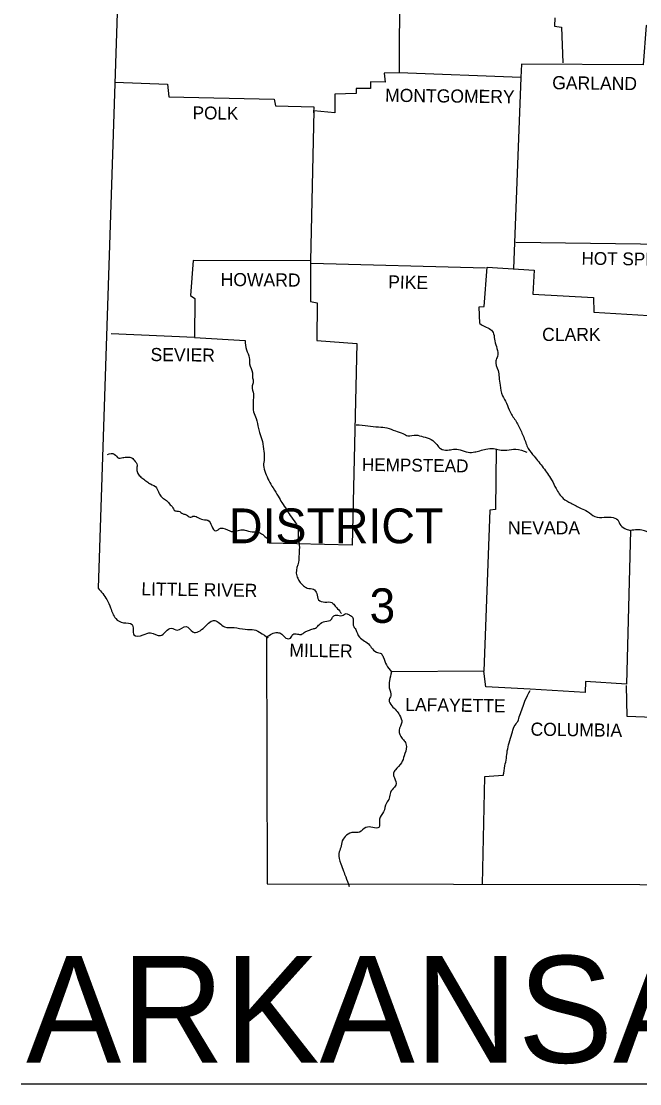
# Model space of a CAD drawing. Extents: x -42408 to 34530, y -43140 to 20491.
# Drawn here: x -17742 to -16626, y 2539 to 4456 of the extents above; entities that cross this region are included whole.
import ezdxf

# ---------------------------------------------------------------- set-up
doc = ezdxf.new("R2010")
doc.units = 0
for name, color, linetype in [('1', 7, 'Continuous'), ('2', 7, 'Continuous'), ('3', 7, 'Continuous')]:
    doc.layers.add(name, color=color, linetype=linetype)

msp = doc.modelspace()

# ---------------------------------------------------------------- linework, layer by layer
at = {"layer": '1'}
msp.add_line((-17741.9, 2539.3), (-14228.8, 2539.3), dxfattribs=at)
for points in [[(-17667.8, 5841.4), (-17553.9, 4926.7), (-17603.4, 3433.6)], [(-17058.6, 4685.1), (-17059.7, 4363.2), (-17087.2, 4362.6), (-17085, 4346.1), (-17111.4, 4346.7), (-17111.9, 4334.6), (-17137.8, 4334.6), (-17137.3, 4325.8), (-17175.8, 4324.7), (-17176.3, 4291.1), (-17213.8, 4294.4), (-17219.8, 4023.6), (-17431.7, 4024.2), (-17436.7, 3961.4), (-17428.9, 3955.9), (-17429.5, 3885.5), (-17579.7, 3892.1)], [(-16434.5, 4443), (-16614.4, 4448.5), (-16619.4, 4377.5), (-16839.5, 4378.6), (-16840.6, 4354.9)], [(-16779, 4462.2), (-16779.5, 4447.4), (-16766.9, 4445.2), (-16764.7, 4381.3)], [(-16840.6, 4354.9), (-17059.7, 4363.2)], [(-16840.6, 4354.9), (-16853.4, 4009.5)], [(-17573.1, 4346.1), (-17477.9, 4342.8), (-17475.7, 4319.7), (-17285.3, 4315.8), (-17283.1, 4303.7), (-17213.8, 4301.5), (-17214.3, 4291.1)], [(-16849.4, 4057.7), (-16534.6, 4053.3), (-16528.6, 4105.6), (-16503.8, 4105.6), (-16503.3, 4149.6), (-16384.4, 4148), (-16385.5, 4121.6), (-16354.7, 4119.4), (-16354.7, 4070.9), (-16336, 4069.4)], [(-17219.8, 4023.6), (-17219.8, 3950.4), (-17207.7, 3948.2), (-17208.8, 3880), (-17136.2, 3874.5), (-17145, 3510.7), (-17294.7, 3514.5)], [(-17218.7, 4019.8), (-16903.9, 4011.5)], [(-16914.4, 3910.8), (-16915.5, 3941.1), (-16906.7, 3941.6), (-16901.2, 4012.6), (-16816.4, 4007.1), (-16818.6, 3963.6), (-16709.1, 3957.6), (-16708.5, 3931.2), (-16609.5, 3925.1), (-16592.4, 3895.4), (-16602.9, 3882.2), (-16597.9, 3861.8), (-16239.1, 3848.6)], [(-17429.5, 3885.5), (-17338.1, 3880)], [(-16885.2, 3684.6), (-16886.3, 3575.1), (-16896.2, 3574), (-16907.2, 3283.9)], [(-16642.5, 3537.6), (-16649.6, 3260.3), (-16723.9, 3265.2), (-16724.5, 3244.9), (-16823.6, 3250.9)], [(-17299.1, 3345), (-17298, 2899.8), (-15280.9, 2896.5)], [(-16823.6, 3250.9), (-16903.4, 3255.3), (-16907.2, 3283.9), (-17074, 3282.3)], [(-16413.5, 3193.1), (-16648.5, 3201.9), (-16649.6, 3257.5)], [(-16872, 3095.2), (-16906.1, 3093), (-16910, 2899.2)]]:
    msp.add_lwpolyline(points, dxfattribs=at)
for points in [[(-16914.4, 3910.8), (-16905.6, 3905.3), (-16895.1, 3900.3), (-16889.6, 3892.1), (-16887.4, 3879.4), (-16883.5, 3865.7), (-16882.4, 3851.4), (-16885.7, 3843.6), (-16881.3, 3826), (-16879.7, 3813.9), (-16878, 3799.6), (-16873.6, 3780.4), (-16866.5, 3767.1), (-16859.9, 3751.2), (-16848.9, 3734.1), (-16839.5, 3715.4), (-16835.1, 3705.5), (-16826.9, 3685.1), (-16816.4, 3671.4), (-16799.9, 3650.5), (-16785, 3629), (-16776.8, 3613), (-16764.1, 3595.4), (-16749.8, 3586.6), (-16731.6, 3577.3), (-16720.1, 3571.8), (-16706.9, 3562.4), (-16689.8, 3561.3), (-16677.2, 3561.3), (-16665.6, 3556.4), (-16660.1, 3546.5), (-16650.2, 3539.9), (-16642.5, 3537.6)], [(-17338.1, 3880), (-17335.4, 3863.5), (-17330.4, 3849.1), (-17329.9, 3838.1), (-17324.9, 3821.6), (-17324.9, 3815.6), (-17323.3, 3803.5), (-17325.5, 3796.9), (-17322.7, 3783.7), (-17323.3, 3773.8), (-17323.3, 3765.5), (-17322.7, 3751.7), (-17318.3, 3739.6), (-17313.9, 3721.5), (-17311.2, 3712.1), (-17306.8, 3697.8), (-17304, 3680.2), (-17303.5, 3667), (-17304.6, 3654.9), (-17301.3, 3641.1), (-17295.2, 3627.4), (-17287.5, 3614.1), (-17278.2, 3599.3), (-17271.5, 3587.7), (-17263.3, 3575.1), (-17256.7, 3564.6), (-17246.8, 3551.4), (-17242.4, 3540.4), (-17242.4, 3525), (-17240.2, 3510.7), (-17240.7, 3494.7), (-17241.8, 3480.4), (-17245.7, 3460.6), (-17242.9, 3451.2), (-17232.5, 3437.5), (-17225.9, 3433.6), (-17214.3, 3431.4), (-17208.8, 3423.7), (-17205.5, 3412.2), (-17193.9, 3408.3), (-17181.3, 3407.2), (-17175.2, 3400.6), (-17167, 3391.8), (-17164.2, 3387.4)], [(-17137.3, 3728.1), (-17116.3, 3726.4), (-17097.1, 3724.2), (-17082.2, 3722.6), (-17066.8, 3717.1), (-17053.1, 3712.1), (-17044.3, 3708.3), (-17029.4, 3709.4), (-17016.7, 3706.6), (-17002.4, 3701.7), (-16992, 3692.3), (-16985.4, 3685.1), (-16972.7, 3682.4), (-16962.2, 3684), (-16949.6, 3682.9), (-16935.3, 3678.5), (-16923.7, 3679.1), (-16914.4, 3681.3), (-16903.4, 3684), (-16889.6, 3685.1), (-16879.1, 3682.9), (-16865.4, 3682.4), (-16849.4, 3684), (-16829.6, 3678.5)], [(-17586.3, 3674.7), (-17574.2, 3675.2), (-17566, 3668.1), (-17561, 3668.6), (-17552.2, 3669.7), (-17544, 3669.2), (-17537.9, 3664.2), (-17533, 3655.4), (-17533.5, 3647.2), (-17533, 3643.9), (-17529.1, 3636.7), (-17522.5, 3631.2), (-17515.4, 3625.7), (-17508.7, 3621.3), (-17497.7, 3614.1), (-17496.6, 3611.9), (-17492.2, 3603.1), (-17486.7, 3596), (-17480.1, 3591.6), (-17473, 3583.9), (-17469.7, 3580.6), (-17464.2, 3572.9), (-17458.1, 3572.3), (-17449.9, 3567.4), (-17443.8, 3565.7), (-17437.2, 3561.3), (-17430.6, 3563.5), (-17422.3, 3560.2), (-17411.3, 3556.9), (-17405.3, 3555.8), (-17398.1, 3545.4), (-17391, 3536.5), (-17382.2, 3541.5), (-17365.7, 3536.5), (-17355.2, 3536), (-17345.8, 3538.7), (-17338.7, 3538.2), (-17325.5, 3534.9), (-17317.2, 3534.9), (-17308.4, 3531.6), (-17300.2, 3525), (-17294.7, 3517.8), (-17294.7, 3514.5)], [(-16514.3, 3566.3), (-16528.6, 3556.9), (-16539.6, 3552.5), (-16547.8, 3549.8), (-16555.5, 3547.6), (-16565.4, 3541), (-16573.1, 3535.4), (-16583.6, 3530.5), (-16593.5, 3527.2), (-16605.6, 3531), (-16612.2, 3534.9), (-16619.4, 3537.6), (-16642.5, 3537.6)], [(-17603.4, 3433.6), (-17587.5, 3412.7), (-17580.8, 3397.9), (-17571.5, 3378.6), (-17557.7, 3370.9), (-17541.8, 3368.1), (-17538.5, 3349.4), (-17522, 3348.9), (-17508.7, 3352.7), (-17490.6, 3347.8), (-17471.3, 3361), (-17460.3, 3357.7), (-17444.4, 3364.3), (-17432.3, 3354.4), (-17411.3, 3363.2), (-17392.6, 3375.3), (-17375, 3363.7), (-17358, 3362.1), (-17337.6, 3359.3), (-17321.6, 3358.2), (-17307.3, 3351.1), (-17296.9, 3343.9), (-17299.1, 3345)], [(-17299.1, 3345), (-17279.8, 3353.3), (-17271.5, 3350.5), (-17264.4, 3343.4), (-17256.1, 3343.4), (-17251.7, 3350), (-17243.5, 3350.5), (-17236.9, 3350), (-17229.7, 3354.4), (-17223.7, 3357.1), (-17215.4, 3359.9), (-17209.4, 3362.1), (-17203.9, 3368.1), (-17193.9, 3373.1), (-17182.4, 3376.9), (-17179.1, 3382.4), (-17173.6, 3384.7), (-17162.6, 3384.1), (-17155.4, 3387.4), (-17149.4, 3384.7), (-17143.9, 3380.8), (-17142.8, 3366.5), (-17138.4, 3358.8), (-17131.8, 3345), (-17122.4, 3337.9), (-17113.6, 3330.7), (-17110.3, 3326.3), (-17100.9, 3318.1), (-17092.7, 3315.3), (-17088.8, 3309.3), (-17082.8, 3294.9), (-17074, 3282.3)], [(-17074, 3282.3), (-17077.3, 3266.3), (-17077.8, 3253.7), (-17075.1, 3238.8), (-17077.8, 3231.7), (-17073.4, 3221.2), (-17065.2, 3212.9), (-17059.1, 3204.1), (-17055.3, 3191.5), (-17060.2, 3177.2), (-17054.7, 3162.3), (-17049.8, 3156.8), (-17047, 3148), (-17050.9, 3130.9), (-17055.8, 3118.3), (-17066.8, 3105.6), (-17070.1, 3099.6), (-17068.5, 3091.3), (-17065.7, 3078.1), (-17068.5, 3074.3), (-17075.6, 3064.9), (-17077.8, 3054.4), (-17082.8, 3045.6), (-17088.3, 3029.7), (-17095.4, 3016.5), (-17096.5, 3001.6), (-17107.5, 3001.6), (-17120.2, 3001.6), (-17131.8, 2993.3), (-17142.2, 2992.8), (-17154.9, 2987.8), (-17162.6, 2977.4), (-17165.3, 2965.8), (-17168.6, 2954.8), (-17165.3, 2936.1), (-17160.4, 2922.9), (-17156.5, 2912.4), (-17149.9, 2895.4)], [(-16872, 3095.2), (-16869.2, 3112.8), (-16866.5, 3126.5), (-16864.8, 3139.7), (-16861.5, 3154.6), (-16856.6, 3170.6), (-16852.2, 3183.8), (-16846.1, 3193.1), (-16842.3, 3204.1), (-16837.3, 3217.3), (-16832.4, 3231.1), (-16823.6, 3248.7)]]:
    msp.add_spline(points, degree=3, dxfattribs=at)

# ---------------------------------------------------------------- texts
at = {"layer": '2'}
for s, height, rotation, p in [('GARLAND', 23.67, 359.3658, (-16783.9, 4333.5)), ('MONTGOMERY', 23.67, 359.2944, (-17085.5, 4310.9)), ('POLK', 23.11, 359.2152, (-17432.8, 4279.5)), ('HOT SPRING', 23.11, 359.2216, (-16731.1, 4017)), ('HOWARD', 23.67, 359.5145, (-17382.2, 3978.5)), ('PIKE', 23.66, 359.0452, (-17080, 3974.1)), ('SEVIER', 23.67, 359.4271, (-17508.7, 3843.1)), ('HEMPSTEAD', 23.11, 359.1885, (-17127.4, 3645)), ('LITTLE RIVER', 23.666, 359.1697, (-17525.3, 3420.4)), ('MILLER', 23.66, 359.1319, (-17258.3, 3309.8)), ('LAFAYETTE', 23.66, 359.1839, (-17049.2, 3211.8)), ('COLUMBIA', 23.66, 359.2125, (-16823, 3167.3))]:
    msp.add_text(s, height=height, rotation=rotation, dxfattribs=at).set_placement(p)
for s, height, p in [('CLARK', 23.67, (-16802, 3879.3)), ('NEVADA', 23.67, (-16863.7, 3530.5)), ('ARKANSAS HIGHWAY DISTRICT 6', 192.623, (-17733.2, 2577.3))]:
    msp.add_text(s, height=height, dxfattribs=at).set_placement(p)
at = {"layer": '3'}
for s, height, p in [('DISTRICT', 62.74, (-17367.1, 3514.4)), ('3', 62.2, (-17113.4, 3370.8))]:
    msp.add_text(s, height=height, dxfattribs=at).set_placement(p)

doc.saveas('drawing.dxf')
